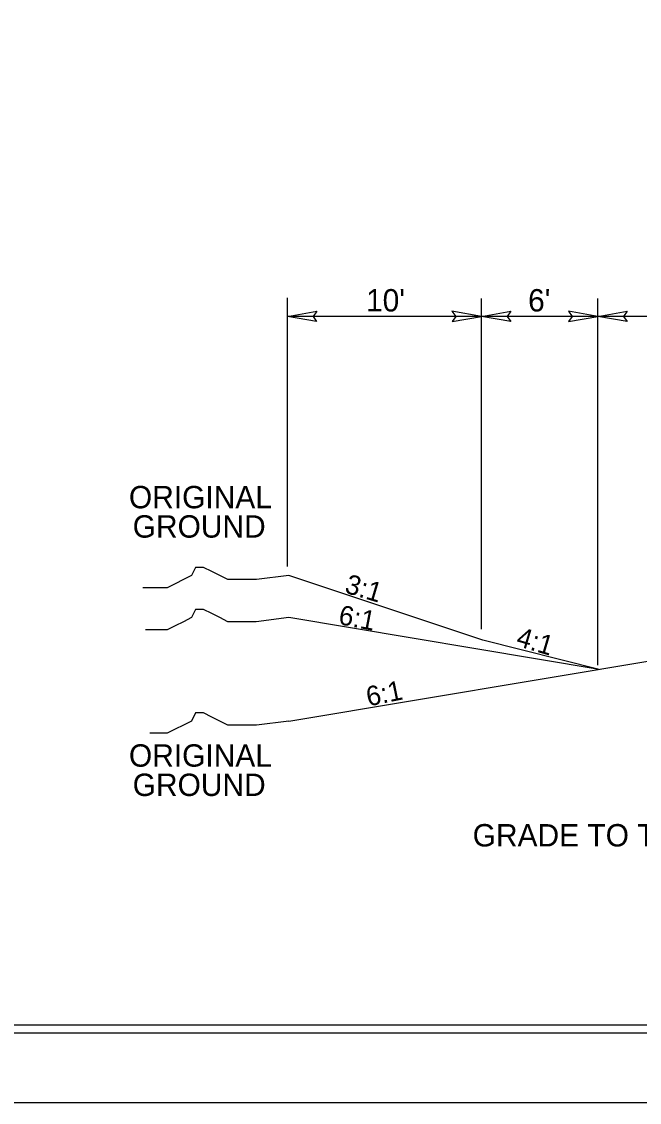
# Model space of a CAD drawing. Extents: x 2176156 to 2177167, y 76401 to 76644.
# Drawn here: x 2176765.8 to 2176797.7, y 76454.5 to 76510.2 of the extents above; entities that cross this region are included whole.
import ezdxf

# ---------------------------------------------------------------- set-up
doc = ezdxf.new("R2010")
doc.units = 0
for name, color, linetype in [('Exist Roads Curbs', 7, 'Continuous'), ('Exist Roads EOP Other', 7, 'Continuous'), ('Exist Roads Soil', 7, 'Continuous'), ('Exist Structure Minor Culvert Topo', 7, 'Continuous'), ('Old_Level_1', 7, 'Continuous'), ('Old_Level_3', 7, 'Continuous'), ('Sheet Cutting Line CELL', 7, 'Continuous'), ('Sheet Data Field CELL', 7, 'Continuous'), ('Sheet Plot Border Outside CELL', 7, 'Continuous'), ('Sheet Sticker Exception Certification CELL', 7, 'Continuous')]:
    doc.layers.add(name, color=color, linetype=linetype)

msp = doc.modelspace()

# ---------------------------------------------------------------- linework, layer by layer
at = {"layer": 'Exist Roads Curbs'}
for points in [[(2176779.59, 76481.63), (2176777.92, 76481.422), (2176777.502, 76481.422), (2176776.875, 76481.422), (2176776.457, 76481.422), (2176776.039, 76481.63), (2176775.622, 76481.84), (2176775.204, 76482.049), (2176774.786, 76482.049), (2176774.577, 76481.63), (2176774.159, 76481.422), (2176773.741, 76481.212), (2176773.324, 76481.004), (2176772.906, 76481.004), (2176772.489, 76481.004), (2176772.073, 76481.004)], [(2176779.59, 76479.463), (2176777.919, 76479.255), (2176777.502, 76479.255), (2176776.875, 76479.255), (2176776.457, 76479.255), (2176776.039, 76479.463), (2176775.622, 76479.673), (2176775.204, 76479.882), (2176774.786, 76479.882), (2176774.577, 76479.463), (2176774.159, 76479.255), (2176773.741, 76479.045), (2176773.324, 76478.837), (2176772.906, 76478.837), (2176772.488, 76478.837), (2176772.206, 76478.837)], [(2176779.59, 76474.13), (2176777.92, 76473.922), (2176777.502, 76473.922), (2176776.875, 76473.922), (2176776.457, 76473.922), (2176776.039, 76474.13), (2176775.622, 76474.34), (2176775.204, 76474.549), (2176774.786, 76474.549), (2176774.577, 76474.13), (2176774.159, 76473.922), (2176773.741, 76473.712), (2176773.324, 76473.504), (2176772.906, 76473.504), (2176772.489, 76473.504), (2176772.427, 76473.504)]]:
    msp.add_lwpolyline(points, dxfattribs=at)
at = {"layer": 'Exist Roads EOP Other'}
for p, q in [((2176789.59, 76478.297), (2176779.59, 76481.63)), ((2176795.59, 76476.797), (2176789.59, 76478.297))]:
    msp.add_line(p, q, dxfattribs=at)
at = {"layer": 'Exist Roads Soil'}
for p, q in [((2176795.59, 76476.797), (2176779.59, 76479.463)), ((2176779.59, 76474.13), (2176807.542, 76478.788))]:
    msp.add_line(p, q, dxfattribs=at)
at = {"layer": 'Old_Level_1'}
for points in [[(2176781.028, 76494.732), (2176779.519, 76494.992), (2176781.037, 76495.261), (2176780.844, 76494.992)], [(2176788.009, 76494.732), (2176789.519, 76494.992), (2176788.001, 76495.261), (2176788.194, 76494.992)], [(2176791.028, 76494.732), (2176789.519, 76494.992), (2176791.037, 76495.261), (2176790.844, 76494.992)], [(2176794.009, 76494.732), (2176795.519, 76494.992), (2176794.001, 76495.261), (2176794.194, 76494.992)], [(2176797.028, 76494.732), (2176795.519, 76494.992), (2176797.037, 76495.261), (2176796.844, 76494.992)]]:
    msp.add_lwpolyline(points, close=True, dxfattribs=at)
at = {"layer": 'Old_Level_3'}
for p, q in [((2176779.519, 76482.098), (2176779.519, 76495.946)), ((2176789.519, 76478.868), (2176789.519, 76495.92)), ((2176795.519, 76477.01), (2176795.519, 76495.92)), ((2176789.519, 76494.992), (2176779.519, 76494.992)), ((2176795.519, 76494.992), (2176789.519, 76494.992)), ((2176807.519, 76494.992), (2176795.519, 76494.992))]:
    msp.add_line(p, q, dxfattribs=at)
at = {"layer": 'Sheet Cutting Line CELL'}
msp.add_lwpolyline([(2176898.707, 76630.475), (2176629.267, 76630.475), (2176629.267, 76454.475), (2176898.707, 76454.475)], close=True, dxfattribs=at)
at = {"layer": 'Sheet Data Field CELL'}
msp.add_lwpolyline([(2176895.987, 76626.475), (2176655.987, 76626.475), (2176655.987, 76458.475), (2176895.987, 76458.475)], close=True, dxfattribs=at)
at = {"layer": 'Sheet Plot Border Outside CELL'}
msp.add_lwpolyline([(2176897.987, 76626.883), (2176631.347, 76626.883), (2176631.347, 76458.067), (2176897.987, 76458.067)], close=True, dxfattribs=at)
at = {"layer": 'Sheet Sticker Exception Certification CELL'}
msp.add_line((2176629.267, 76454.475), (2176898.707, 76454.475), dxfattribs=at)

# ---------------------------------------------------------------- texts
at = {"layer": 'Exist Roads Curbs'}
for s, rotation, p in [('3:1', 343.5351, (2176782.426, 76480.763)), ('6:1', 349.1832, (2176782.107, 76479.135)), ('4:1', 343.5351, (2176791.257, 76478.03)), ('6:1', 11.4865, (2176783.693, 76474.885))]:
    msp.add_text(s, height=1.0064, rotation=rotation, dxfattribs=at).set_placement(p)
at = {"layer": 'Exist Structure Minor Culvert Topo'}
for s, height, p in [("10'", 1.1533, (2176783.571, 76495.245)), ("6'", 1.1533, (2176791.925, 76495.245)), ('ORIGINAL', 1.1533, (2176771.353, 76485.099)), ('GROUND', 1.1533, (2176771.547, 76483.587)), ('ORIGINAL', 1.1533, (2176771.353, 76471.78)), ('GROUND', 1.1533, (2176771.547, 76470.269)), ('GRADE TO THIS LINE', 1.15334, (2176789.07, 76467.668))]:
    msp.add_text(s, height=height, dxfattribs=at).set_placement(p)

doc.saveas('drawing.dxf')
